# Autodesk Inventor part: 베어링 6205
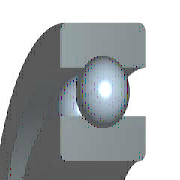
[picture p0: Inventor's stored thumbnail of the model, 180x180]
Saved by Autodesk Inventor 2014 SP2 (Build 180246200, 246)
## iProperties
IsCustomPart: 1
Company: 한국ATC센터
Created: 2014-11
Part Number: 베어링 6205
Material: 강, 연강
Description: 깊은 그루브 볼 베어링
Document SubType Name: Modeling
Standard: KS B 2023
Designer: KYOUNG IL JANG
Standards Organization: KS
Language: ko-KR
Size Designation: 6205 - 25 x 52 x 15
Categories: <MemberInstance><Categories><Category DisplayName="샤프트 부품" InternalName="7f7aeb1f-a693-4053-b835-cee3144e0d98" Mnemonic="SHFT"><Category DisplayName="베어링" Inter
Density: 7.86 g/cm^3
Mass: 129.543 g
Surface Area: 107.326 cm^2
Volume: 16.4813 cm^3
Appearance: 강철
Author: KYOUNG IL JANG
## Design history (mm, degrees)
sketch "스케치" dims "d0" = 7.02 (= -0.26 x WD + 0.26 x BD)
  geometry: L1 (3.99, 19.25)-(11.01, 19.25); L2 (7.5, 19.25)-(7.5, 15.74); L3 (7.5, 19.25)-(7.5, 22.76); L4 (4.892, 16.901)-(0, 16.901); L5 (0, 12.5)-(15, 12.5); L6 (4.892, 21.599)-(0, 21.599); L7 (0, 26)-(15, 26); L8 (15, 12.5)-(15, 16.901); L9 (10.108, 16.901)-(15, 16.901); L10 (10.108, 21.599)-(15, 21.599); L11 (15, 26)-(15, 21.599); L12 (-1.4, 0)-(8.4, 0) reference; L13 (0, -0.3)-(0, 5.3) reference
  constraints: 22 end point, 4 point on line, 2 collinear, 2 perpendicular, 2 symmetric about line, 1 midpoint, 1 parallel, 14 other
  dimensions: "d9" = 25 diameter of L5 L12 (= WD); "d11" = 52 diameter of L7 L12 (= BD); "d12" = 15 distance between parallel lines of L8 L13 (= KB); "d13" = 33.802 diameter of L9 L12 (= 0.326 x BD + 0.674 x WD)
revolve "본체" stored, may be unused: angle "d6" = 90 deg
revolve "볼" stored, may be unused: angle "d7" = 90 deg
pattern_circular "IDS_ARRAYBALL[SIMPL:T]" dims angle "d3" = 360 deg
body "Solid1"
fillet "모깎기1" dims "d1" = 1 (= KRS)
other parameters: "WD" = 25 [user parameter; used in 5 equation terms], "BD" = 52 [user parameter; used in 5 equation terms], "KB" = 15 [user parameter; used in 1 equation term], "KRS" = 1 [user parameter; used in 1 equation term], "d4" = 0, "d5" = 0, "d8" = 0, "d14" = 0, "d15" = 0, "BBA" = 0 [user parameter], "BC0" = 7800000 [user parameter], "BC" = 1.4e+07 [user parameter], "BR" = 26 (= 0.5 x BD) [user parameter], "WR" = 12.5 (= 0.5 x WD) [user parameter]
